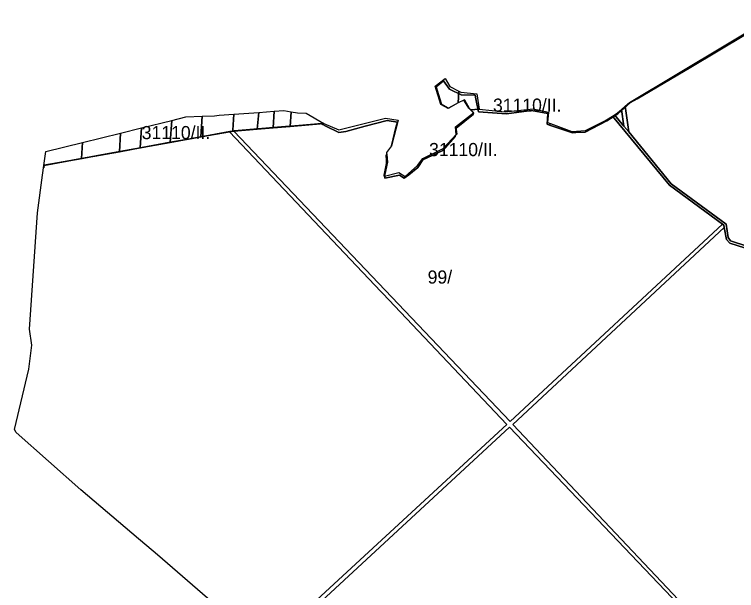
# Model space of a CAD drawing. Extents: x -535894 to -532827, y -1165802 to -1163635.
# Drawn here: x -535894 to -535071, y -1164561 to -1163904 of the extents above; entities that cross this region are included whole.
import ezdxf

# ---------------------------------------------------------------- set-up
doc = ezdxf.new("R2010")
doc.units = 0
for name, color, linetype in [('BPEJ_s', 7, 'Continuous'), ('ostatni_s', 7, 'Continuous'), ('PUPFL_s', 7, 'Continuous'), ('zahrada_s', 7, 'Continuous')]:
    doc.layers.add(name, color=color, linetype=linetype)

msp = doc.modelspace()

# ---------------------------------------------------------------- linework, layer by layer
at = {"layer": 'BPEJ_s'}
for points in [[(-535060.95, -1163926.6), (-535123.09, -1163964.15), (-535184.283, -1164000), (-535191.879, -1164004.45), (-535206.27, -1164017.13), (-535218.879, -1164025.24), (-535243.809, -1164038.08), (-535254.323, -1164038.581), (-535257.966, -1164038.797), (-535284.325, -1164030.09), (-535284.14, -1164029.836), (-535283.01, -1164028.29), (-535259.04, -1164037.22), (-535243.35, -1164036.42), (-535221.22, -1164025.37), (-535212.54, -1164019.84), (-535210.13, -1164018.3), (-535206.91, -1164016.24), (-535202.21, -1164012.17), (-535198.09, -1164008.6), (-535193.05, -1164004.23), (-535025.69, -1163903.86)], [(-535716.39, -1164049.703), (-535696.084, -1164046.016), (-535683.928, -1164043.81), (-535681.446, -1164043.359), (-535648.804, -1164037.434), (-535643.748, -1164036.759), (-535616.982, -1164034.374), (-535598.97, -1164032.888), (-535585.382, -1164031.761), (-535579.28, -1164031.255), (-535552.117, -1164029.012), (-535544.813, -1164028.409), (-535544.696, -1164028.399), (-535542.809, -1164029.44), (-535540.105, -1164030.779), (-535524.399, -1164038.55), (-535516.73, -1164037.45), (-535494.317, -1164031.21), (-535469.421, -1164024.672), (-535457.62, -1164026.594), (-535457.976, -1164028.066), (-535459.219, -1164031.44), (-535464.556, -1164053.828), (-535470.22, -1164061.35), (-535469.981, -1164063.742), (-535470.62, -1164064.63), (-535470.176, -1164070.177), (-535470.176, -1164073.747), (-535472.784, -1164087.2), (-535472.448, -1164089.047), (-535472.097, -1164089.102), (-535472.09, -1164090.59), (-535455.399, -1164087.06), (-535450.099, -1164090.67), (-535444.6, -1164086.66), (-535434.39, -1164078.45), (-535428.91, -1164069.77), (-535417.399, -1164064.36), (-535406.09, -1164059.25), (-535391.809, -1164043.17), (-535391.84, -1164042.287), (-535390.168, -1164040.516), (-535390.655, -1164035.023), (-535390.789, -1164033.504), (-535370.899, -1164017.75), (-535371.884, -1164017.027), (-535370.441, -1164015.92), (-535373.849, -1164012.543), (-535375.752, -1164010.661), (-535381.401, -1164001.199), (-535381.946, -1164001.486), (-535381.95, -1164001.48), (-535388.33, -1164004.85), (-535399.494, -1164010.742), (-535407.605, -1164006.231), (-535409.51, -1164000), (-535413.67, -1163986.392), (-535405.065, -1163979.77), (-535398.479, -1163989.104), (-535396.874, -1163989.857), (-535385.71, -1163995.36), (-535385.116, -1163995.378), (-535385.031, -1163995.419), (-535369.114, -1163995.968), (-535368.296, -1164000), (-535365.272, -1164014.912), (-535333.437, -1164017.383), (-535304.895, -1164013.539), (-535286.233, -1164016.834), (-535287.057, -1164029.188), (-535284.325, -1164030.09), (-535257.966, -1164038.797), (-535254.323, -1164038.581), (-535243.809, -1164038.08), (-535218.879, -1164025.24), (-535206.27, -1164017.13), (-535191.879, -1164004.45), (-535184.283, -1164000), (-535123.09, -1163964.15), (-535060.95, -1163926.6)], [(-535608.87, -1164626.28), (-535731.43, -1164520.35), (-535750.75, -1164503.89), (-535752.85, -1164502.11), (-535818.64, -1164446.08), (-535892.52, -1164380.76), (-535894.37, -1164377.39), (-535877.94, -1164308.59), (-535874.71, -1164281.05), (-535877.05, -1164262.85), (-535867.9, -1164130.03), (-535862.54, -1164087.02), (-535861.354, -1164078.82), (-535860.832, -1164078.707), (-535860.42, -1164075.851), (-535817.263, -1164068.017), (-535799.13, -1164064.723), (-535774.102, -1164060.177), (-535774.054, -1164060.168), (-535750.51, -1164055.897), (-535716.39, -1164049.703)]]:
    msp.add_lwpolyline(points, dxfattribs=at)
for points in [[(-535403.43, -1163977.11), (-535398.02, -1163986.08), (-535387.79, -1163991.42), (-535385.61, -1163992.56), (-535367.36, -1163994.47), (-535364.66, -1164011.94), (-535335, -1164014.8), (-535302.8, -1164011.53), (-535285.57, -1164015.37), (-535286.58, -1164026.96), (-535283.01, -1164028.29), (-535284.14, -1164029.836), (-535284.325, -1164030.09), (-535287.057, -1164029.188), (-535286.233, -1164016.834), (-535304.895, -1164013.539), (-535333.437, -1164017.383), (-535365.272, -1164014.912), (-535368.296, -1164000), (-535369.114, -1163995.968), (-535385.031, -1163995.419), (-535385.116, -1163995.378), (-535385.71, -1163995.36), (-535396.874, -1163989.857), (-535398.479, -1163989.104), (-535405.065, -1163979.77), (-535413.67, -1163986.392), (-535409.51, -1164000), (-535407.605, -1164006.231), (-535399.494, -1164010.742), (-535400.04, -1164011.03), (-535408.16, -1164006.52), (-535414.57, -1163985.52)], [(-535444.6, -1164086.66), (-535450.099, -1164090.67), (-535455.399, -1164087.06), (-535472.09, -1164090.59), (-535472.097, -1164089.102), (-535472.448, -1164089.047), (-535472.784, -1164087.2), (-535470.176, -1164073.747), (-535470.176, -1164070.177), (-535470.62, -1164064.63), (-535469.981, -1164063.742), (-535469.11, -1164072.45), (-535472.32, -1164088.29), (-535456.22, -1164084.32), (-535448.87, -1164088.63), (-535434.91, -1164076.33), (-535428.61, -1164068.13), (-535405.71, -1164056.67), (-535390.72, -1164040.8), (-535391.51, -1164031.93), (-535370.99, -1164016.2), (-535374.4, -1164012.83), (-535376.31, -1164010.95), (-535381.946, -1164001.486), (-535381.401, -1164001.199), (-535375.752, -1164010.661), (-535373.849, -1164012.543), (-535370.441, -1164015.92), (-535371.884, -1164017.027), (-535370.899, -1164017.75), (-535390.789, -1164033.504), (-535390.655, -1164035.023), (-535390.168, -1164040.516), (-535391.84, -1164042.287), (-535391.809, -1164043.17), (-535406.09, -1164059.25), (-535417.399, -1164064.36), (-535428.91, -1164069.77), (-535434.39, -1164078.45)], [(-535541.53, -1164028.39), (-535524.35, -1164035.36), (-535471.34, -1164022.13), (-535456.81, -1164024.35), (-535464.43, -1164053.66), (-535464.556, -1164053.828), (-535459.219, -1164031.44), (-535457.976, -1164028.066), (-535457.62, -1164026.594), (-535469.421, -1164024.672), (-535494.317, -1164031.21), (-535516.73, -1164037.45), (-535524.399, -1164038.55), (-535540.105, -1164030.779), (-535542.809, -1164029.44), (-535544.696, -1164028.399), (-535544.813, -1164028.409), (-535552.117, -1164029.012), (-535579.28, -1164031.255), (-535585.382, -1164031.761), (-535598.97, -1164032.888), (-535616.982, -1164034.374), (-535643.748, -1164036.759), (-535648.804, -1164037.434), (-535681.446, -1164043.359), (-535683.928, -1164043.81), (-535696.084, -1164046.016), (-535716.39, -1164049.703), (-535750.51, -1164055.897), (-535774.054, -1164060.168), (-535774.102, -1164060.177), (-535799.13, -1164064.723), (-535817.263, -1164068.017), (-535860.42, -1164075.851), (-535860.832, -1164078.707), (-535861.354, -1164078.82), (-535860.97, -1164076.16), (-535858.66, -1164060.16), (-535816.78, -1164049.85), (-535773.53, -1164039.2), (-535749.49, -1164033.28), (-535714.97, -1164024.78), (-535698.8, -1164020.81), (-535680.43, -1164019.97), (-535666.39, -1164019.34), (-535661, -1164018.94), (-535644.41, -1164017.71), (-535615.79, -1164015.65), (-535598.07, -1164014.27), (-535587.24, -1164013.46), (-535579.04, -1164014.78), (-535571.78, -1164015.94), (-535561.92, -1164016.58)]]:
    msp.add_lwpolyline(points, close=True, dxfattribs=at)
at = {"layer": 'ostatni_s'}
msp.add_lwpolyline([(-535198.09, -1164008.6), (-535194.06, -1164037.89), (-535199.44, -1164031.33), (-535202.21, -1164012.17)], close=True, dxfattribs=at)
msp.add_lwpolyline([(-535038.07, -1164177.61), (-535078.73, -1164164.6), (-535082.44, -1164160.63), (-535085.14, -1164146.96), (-535085.71, -1164144.07), (-535086.95, -1164143.16), (-535147.62, -1164098.64), (-535212.54, -1164019.84), (-535210.13, -1164018.3), (-535199.44, -1164031.33), (-535194.06, -1164037.89), (-535145.65, -1164096.91), (-535082.87, -1164143.2), (-535080.49, -1164158.48), (-535077.79, -1164162.19), (-535037.17, -1164175.56)], dxfattribs=at)
at = {"layer": 'PUPFL_s'}
for points in [[(-535037.17, -1164175.56), (-535077.79, -1164162.19), (-535080.49, -1164158.48), (-535082.87, -1164143.2), (-535145.65, -1164096.91), (-535194.06, -1164037.89), (-535198.09, -1164008.6), (-535193.05, -1164004.23), (-535025.69, -1163903.86)], [(-535117.95, -1164592.03), (-535326.28, -1164371.53), (-535085.14, -1164146.96), (-535082.44, -1164160.63), (-535078.73, -1164164.6), (-535038.07, -1164177.61)]]:
    msp.add_lwpolyline(points, dxfattribs=at)
for points in [[(-535403.43, -1163977.11), (-535398.02, -1163986.08), (-535387.79, -1163991.42), (-535388.33, -1164004.85), (-535400.04, -1164011.03), (-535408.16, -1164006.52), (-535414.57, -1163985.52)], [(-535385.61, -1163992.56), (-535367.36, -1163994.47), (-535364.66, -1164011.94), (-535374.4, -1164012.83), (-535376.31, -1164010.95), (-535381.95, -1164001.48), (-535388.33, -1164004.85), (-535387.79, -1163991.42)], [(-535364.66, -1164011.94), (-535335, -1164014.8), (-535302.8, -1164011.53), (-535285.57, -1164015.37), (-535286.58, -1164026.96), (-535259.04, -1164037.22), (-535243.35, -1164036.42), (-535221.22, -1164025.37), (-535212.54, -1164019.84), (-535147.62, -1164098.64), (-535086.95, -1164143.16), (-535329.29, -1164368.36), (-535644.3, -1164037.06), (-535617.54, -1164034.67), (-535599.52, -1164033.18), (-535579.83, -1164031.55), (-535541.53, -1164028.39), (-535524.35, -1164035.36), (-535471.34, -1164022.13), (-535456.81, -1164024.35), (-535464.43, -1164053.66), (-535470.22, -1164061.35), (-535469.11, -1164072.45), (-535472.32, -1164088.29), (-535456.22, -1164084.32), (-535448.87, -1164088.63), (-535434.91, -1164076.33), (-535428.61, -1164068.13), (-535405.71, -1164056.67), (-535390.72, -1164040.8), (-535391.51, -1164031.93), (-535370.99, -1164016.2), (-535374.4, -1164012.83)], [(-535202.21, -1164012.17), (-535199.44, -1164031.33), (-535210.13, -1164018.3), (-535206.91, -1164016.24)], [(-535649.36, -1164037.73), (-535476.52, -1164220.08), (-535474.5, -1164222.2), (-535332.86, -1164371.64), (-535608.87, -1164626.28), (-535731.43, -1164520.35), (-535750.75, -1164503.89), (-535752.85, -1164502.11), (-535818.64, -1164446.08), (-535892.52, -1164380.76), (-535894.37, -1164377.39), (-535877.94, -1164308.59), (-535874.71, -1164281.05), (-535877.05, -1164262.85), (-535867.9, -1164130.03), (-535862.54, -1164087.02), (-535860.97, -1164076.16), (-535817.82, -1164068.33), (-535774.61, -1164060.48), (-535751.06, -1164056.2), (-535716.94, -1164050.01), (-535682, -1164043.66)], [(-535644.3, -1164037.06), (-535329.29, -1164368.36), (-535086.95, -1164143.16), (-535085.71, -1164144.07), (-535085.14, -1164146.96), (-535326.28, -1164371.53), (-535117.95, -1164592.03), (-535121.76, -1164593.37), (-535329.84, -1164374.82), (-535605.04, -1164629.61), (-535608.87, -1164626.28), (-535332.86, -1164371.64), (-535474.5, -1164222.2), (-535476.52, -1164220.08), (-535649.36, -1164037.73)], [(-535121.76, -1164593.37), (-535124.4, -1164594.3), (-535157.57, -1164608.35), (-535174.63, -1164617.97), (-535226.37, -1164662.4), (-535265.14, -1164694.54), (-535274.36, -1164699.8), (-535299.42, -1164711.94), (-535322.24, -1164718.04), (-535337.8, -1164722.86), (-535434.81, -1164774.69), (-535538.55, -1164687.07), (-535605.04, -1164629.61), (-535329.84, -1164374.82)]]:
    msp.add_lwpolyline(points, close=True, dxfattribs=at)
at = {"layer": 'zahrada_s'}
for points in [[(-535598.07, -1164014.27), (-535599.52, -1164033.18), (-535617.54, -1164034.67), (-535615.79, -1164015.65)], [(-535587.24, -1164013.46), (-535579.04, -1164014.78), (-535579.83, -1164031.55), (-535599.52, -1164033.18), (-535598.07, -1164014.27)], [(-535680.43, -1164019.97), (-535682, -1164043.66), (-535716.94, -1164050.01), (-535714.97, -1164024.78), (-535698.8, -1164020.81)], [(-535644.41, -1164017.71), (-535645.29, -1164035.98), (-535644.3, -1164037.06), (-535649.36, -1164037.73), (-535682, -1164043.66), (-535680.43, -1164019.97), (-535666.39, -1164019.34), (-535661, -1164018.94)], [(-535615.79, -1164015.65), (-535617.54, -1164034.67), (-535644.3, -1164037.06), (-535645.29, -1164035.98), (-535644.41, -1164017.71)], [(-535571.78, -1164015.94), (-535561.92, -1164016.58), (-535541.53, -1164028.39), (-535579.83, -1164031.55), (-535579.04, -1164014.78)], [(-535714.97, -1164024.78), (-535716.94, -1164050.01), (-535751.06, -1164056.2), (-535749.49, -1164033.28)], [(-535773.53, -1164039.2), (-535774.61, -1164060.48), (-535817.82, -1164068.33), (-535816.78, -1164049.85)], [(-535749.49, -1164033.28), (-535751.06, -1164056.2), (-535774.61, -1164060.48), (-535773.53, -1164039.2)], [(-535816.78, -1164049.85), (-535817.82, -1164068.33), (-535860.97, -1164076.16), (-535858.66, -1164060.16)]]:
    msp.add_lwpolyline(points, close=True, dxfattribs=at)

# ---------------------------------------------------------------- texts
at = {"layer": 'BPEJ_s'}
for s, p in [('31110/II.', (-535348.79, -1164014.831)), ('31110/II.', (-535749.24, -1164046.14)), ('31110/II.', (-535421.613, -1164065.484)), ('99/', (-535423.272, -1164210.923))]:
    msp.add_text(s, height=15, dxfattribs=at).set_placement(p)

doc.saveas('drawing.dxf')
